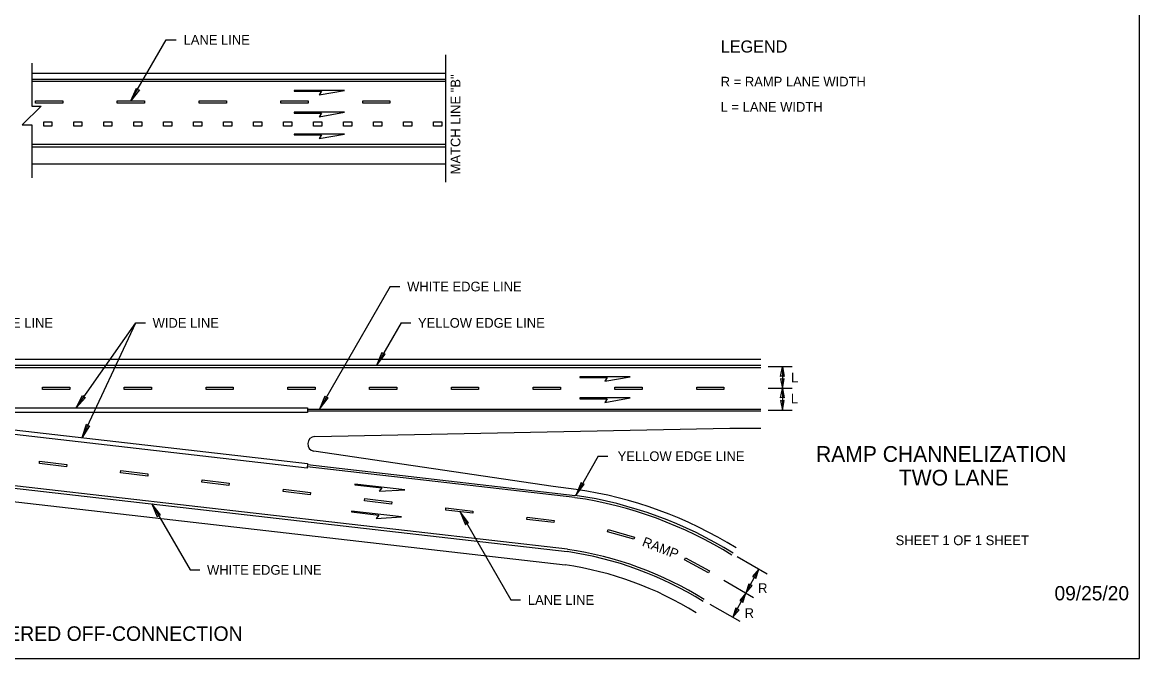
# Model space of a CAD drawing. Extents: x 99862 to 103151, y 100339 to 102415.
# Drawn here: x 101307 to 103151, y 100339 to 101389 of the extents above; entities that cross this region are included whole.
import ezdxf

# ---------------------------------------------------------------- set-up
doc = ezdxf.new("R2010")
doc.units = 0
for name, color, linetype in [('Level 1', 7, 'Continuous'), ('Level 15', 7, 'Continuous'), ('Level 2', 7, 'Continuous'), ('Level 20', 7, 'Continuous'), ('Level 3', 7, 'Continuous'), ('Level 4', 7, 'Continuous'), ('Level 5', 7, 'Continuous'), ('Level 6', 7, 'Continuous'), ('Level 62', 7, 'Continuous')]:
    doc.layers.add(name, color=color, linetype=linetype)

msp = doc.modelspace()

# ---------------------------------------------------------------- linework, layer by layer
at = {"layer": 'Level 1'}
msp.add_lwpolyline([(99862, 100338.8), (103151, 100338.8), (103151, 102414.8), (99862, 102414.8)], close=True, dxfattribs=at)
at = {"layer": 'Level 15'}
for p, q in [((101486, 101259.3), (101544.3, 101360.3)), ((101544.3, 101360.3), (101560.9, 101360.3)), ((101913.9, 100953), (101797.2, 100750.8)), ((101913.9, 100953), (101929.9, 100953)), ((101395.6, 100752.7), (101493.8, 100893)), ((101405.5, 100703.6), (101493.8, 100893)), ((101493.8, 100893), (101509.8, 100893)), ((101931.8, 100893), (101891.3, 100822.8)), ((101931.8, 100893), (101947.8, 100893)), ((102537.9, 100821), (102577.4, 100821)), ((102561.4, 100820.4), (102561.4, 100784.9)), ((102537.9, 100785), (102577.4, 100785)), ((102561.4, 100784.9), (102561.4, 100749)), ((102537.9, 100749), (102577.4, 100749)), ((102257.4, 100672.9), (102220.1, 100608.2)), ((102257.4, 100672.9), (102273.4, 100672.9)), ((101520.7, 100594.2), (101583.6, 100485.3)), ((102029.2, 100581.1), (102113.2, 100435.6)), ((102486.9, 100507.2), (102536.3, 100478.7)), ((101583.6, 100485.3), (101599.6, 100485.3)), ((102501, 100446.9), (102522.4, 100486.7)), ((102464.4, 100468.1), (102513.7, 100439.6)), ((102479.5, 100407.1), (102501, 100446.9)), ((102113.2, 100435.6), (102129.2, 100435.6)), ((102441.8, 100428.9), (102491.1, 100400.4))]:
    msp.add_line(p, q, dxfattribs=at)
for points in [[(101322.2, 101321.9), (101322.2, 101250.7), (101337.7, 101250.7), (101306.7, 101219.7), (101322.2, 101219.7), (101322.2, 101132.6)], [(101337.7, 101250.7), (101306.7, 101219.7)]]:
    msp.add_lwpolyline(points, dxfattribs=at)
for points in [[(101486, 101259.3), (101494.9, 101280.6), (101496.9, 101278.2), (101500.1, 101277.6)], [(101891.3, 100822.8), (101905.4, 100841.2), (101902.3, 100841.8), (101900.2, 100844.2)], [(102561.4, 100820.4), (102564.5, 100804.6), (102561.4, 100805.4), (102558.3, 100804.6)], [(102561.4, 100784.9), (102564.5, 100800.8), (102561.4, 100800), (102558.3, 100800.8)], [(101395.6, 100752.7), (101406.2, 100773.1), (101408.1, 100770.5), (101411.1, 100769.7)], [(101797.2, 100750.8), (101811.3, 100769.2), (101808.1, 100769.8), (101806.1, 100772.2)], [(102561.4, 100784.9), (102564.5, 100769.1), (102561.4, 100769.9), (102558.3, 100769.1)], [(102561.4, 100749), (102564.5, 100764.8), (102561.4, 100764), (102558.3, 100764.8)], [(101405.5, 100703.6), (101412.4, 100725.6), (101414.7, 100723.4), (101417.8, 100723.1)], [(102220.1, 100608.2), (102234.1, 100626.6), (102231, 100627.2), (102228.9, 100629.6)], [(101520.7, 100594.2), (101529.5, 100572.9), (101531.6, 100575.3), (101534.7, 100575.9)], [(102029.2, 100581.1), (102038, 100559.8), (102040.1, 100562.2), (102043.2, 100562.8)], [(102522.4, 100486.7), (102512.2, 100474.3), (102515.3, 100473.4), (102517.7, 100471.3)], [(102501, 100446.9), (102511.2, 100459.4), (102508.1, 100460.2), (102505.8, 100462.3)], [(102501, 100446.9), (102490.8, 100434.5), (102493.8, 100433.6), (102496.2, 100431.5)], [(102479.5, 100407.1), (102489.8, 100419.6), (102486.7, 100420.4), (102484.3, 100422.5)]]:
    msp.add_lwpolyline(points, close=True, dxfattribs=at)
at = {"layer": 'Level 2'}
for p, q in [((101322.3, 101305.4), (102005, 101305.4)), ((101322.2, 101155.4), (102005, 101155.4)), ((100315.1, 100833), (102525.9, 100833))]:
    msp.add_line(p, q, dxfattribs=at)
for points in [[(101789.5, 100705.3), (102474.7, 100719), (102525.9, 100719)], [(102220.8, 100618.2), (102182.7, 100622.7), (101787.9, 100681.4)], [(100315.1, 100673.7), (100633.4, 100673.7), (102202.6, 100493.5)]]:
    msp.add_lwpolyline(points, dxfattribs=at)
for centre, radius, start, end in [((101789.7, 100693.3), 12, 91.1458, 261.5415), ((102121.1, 99936), 689.4, 58.1228, 81.6857), ((102122.4, 99938.8), 560.5, 58.0828, 81.7749)]:
    msp.add_arc(centre, radius, start, end, dxfattribs=at)
at = {"layer": 'Level 3'}
for p, q in [((101322.3, 101295.3), (102005.8, 101295.3)), ((102005.8, 101291.5), (101322.3, 101291.5)), ((102005.8, 101187.3), (101322.2, 101187.3)), ((101322.2, 101183.5), (102005.8, 101183.5)), ((102525.9, 100822.8), (100315.1, 100822.8)), ((100315.1, 100819.1), (102525.9, 100819.1)), ((101777.7, 100750.8), (102525.9, 100750.8)), ((102525.9, 100747.1), (101777.7, 100747.1)), ((102218.8, 100604.6), (101777.1, 100655.3)), ((101777.6, 100659), (102219.3, 100608.3))]:
    msp.add_line(p, q, dxfattribs=at)
msp.add_lwpolyline([(101043.2, 100745.2), (101777.7, 100660.9), (101776.9, 100653.4), (100977.5, 100745.2), (100977.5, 100752.7), (101777.7, 100752.7), (101777.7, 100745.2)], close=True, dxfattribs=at)
for points in [[(102206.4, 100519.3), (100582.6, 100705.6), (100315.1, 100705.6)], [(100315.1, 100701.8), (100582.3, 100701.8), (102205.8, 100515.6)]]:
    msp.add_lwpolyline(points, dxfattribs=at)
for radius, start, end in [(675.6, 58.1147, 81.6808), (679.4, 58.1228, 81.6857), (585.7, 58.1147, 81.6808), (589.4, 58.1147, 81.6808)]:
    msp.add_arc((102121.1, 99936), radius, start, end, dxfattribs=at)
at = {"layer": 'Level 4'}
for points in [[(101328.5, 101259.3), (101373.5, 101259.3), (101373.5, 101255.5), (101328.5, 101255.5)], [(101463.5, 101259.3), (101508.5, 101259.3), (101508.5, 101255.5), (101463.5, 101255.5)], [(101598.5, 101259.3), (101643.5, 101259.3), (101643.5, 101255.5), (101598.5, 101255.5)], [(101733.5, 101259.3), (101778.5, 101259.3), (101778.5, 101255.5), (101733.5, 101255.5)], [(101868.5, 101259.3), (101913.5, 101259.3), (101913.5, 101255.5), (101868.5, 101255.5)], [(101342, 101225.1), (101355.5, 101225.1), (101355.5, 101217.6), (101342, 101217.6)], [(101391.5, 101225.1), (101405, 101225.1), (101405, 101217.6), (101391.5, 101217.6)], [(101441, 101225.1), (101454.5, 101225.1), (101454.5, 101217.6), (101441, 101217.6)], [(101490.5, 101225.1), (101504, 101225.1), (101504, 101217.6), (101490.5, 101217.6)], [(101540, 101225.1), (101553.5, 101225.1), (101553.5, 101217.6), (101540, 101217.6)], [(101589.5, 101225.1), (101603, 101225.1), (101603, 101217.6), (101589.5, 101217.6)], [(101639, 101225.1), (101652.5, 101225.1), (101652.5, 101217.6), (101639, 101217.6)], [(101688.5, 101225.1), (101702, 101225.1), (101702, 101217.6), (101688.5, 101217.6)], [(101738, 101225.1), (101751.5, 101225.1), (101751.5, 101217.6), (101738, 101217.6)], [(101787.5, 101225.1), (101801, 101225.1), (101801, 101217.6), (101787.5, 101217.6)], [(101837, 101225.1), (101850.5, 101225.1), (101850.5, 101217.6), (101837, 101217.6)], [(101886.5, 101225.1), (101900, 101225.1), (101900, 101217.6), (101886.5, 101217.6)], [(101936, 101225.1), (101949.5, 101225.1), (101949.5, 101217.6), (101936, 101217.6)], [(101985.5, 101225.1), (101999, 101225.1), (101999, 101217.6), (101985.5, 101217.6)], [(101339.9, 100786.8), (101384.9, 100786.8), (101384.9, 100783.1), (101339.9, 100783.1)], [(101474.9, 100786.8), (101519.9, 100786.8), (101519.9, 100783.1), (101474.9, 100783.1)], [(101609.9, 100786.8), (101654.9, 100786.8), (101654.9, 100783.1), (101609.9, 100783.1)], [(101744.9, 100786.8), (101789.9, 100786.8), (101789.9, 100783.1), (101744.9, 100783.1)], [(101879.9, 100786.8), (101924.9, 100786.8), (101924.9, 100783.1), (101879.9, 100783.1)], [(102014.9, 100786.8), (102059.9, 100786.8), (102059.9, 100783.1), (102014.9, 100783.1)], [(102149.9, 100786.8), (102194.9, 100786.8), (102194.9, 100783.1), (102149.9, 100783.1)], [(102284.9, 100786.8), (102329.9, 100786.8), (102329.9, 100783.1), (102284.9, 100783.1)], [(102419.9, 100786.8), (102464.9, 100786.8), (102464.9, 100783.1), (102419.9, 100783.1)], [(101335.3, 100664.5), (101380, 100659.4), (101379.6, 100655.6), (101334.9, 100660.8)], [(101469.4, 100649.1), (101514.1, 100644), (101513.7, 100640.2), (101469, 100645.4)], [(101603.5, 100633.7), (101648.2, 100628.6), (101647.8, 100624.8), (101603.1, 100630)], [(101737.7, 100618.3), (101782.4, 100613.2), (101781.9, 100609.4), (101737.2, 100614.6)], [(101871.8, 100602.9), (101916.5, 100597.8), (101916.1, 100594), (101871.3, 100599.2)], [(102005.9, 100587.5), (102050.6, 100582.4), (102050.2, 100578.7), (102005.5, 100583.8)], [(102140, 100572.1), (102184.7, 100567), (102184.3, 100563.3), (102139.6, 100568.4)], [(102273.9, 100551.8), (102317.2, 100539.5), (102316.1, 100535.9), (102272.8, 100548.2)], [(102401.4, 100505.2), (102441, 100483.9), (102439.2, 100480.5), (102399.6, 100501.9)]]:
    msp.add_lwpolyline(points, close=True, dxfattribs=at)
at = {"layer": 'Level 5'}
for points in [[(101755.3, 101275.4), (101800.4, 101275.4), (101796.8, 101269.2), (101838.4, 101276.6), (101755.3, 101276.6)], [(101755.3, 101239.4), (101800.4, 101239.4), (101796.8, 101233.2), (101838.4, 101240.6), (101755.3, 101240.6)], [(101755.3, 101203.4), (101800.4, 101203.4), (101796.8, 101197.2), (101838.4, 101204.6), (101755.3, 101204.6)], [(102226.8, 100803), (102271.9, 100803), (102268.3, 100796.8), (102309.8, 100804.1), (102226.8, 100804.1)], [(102226.7, 100767.9), (102271.8, 100767.9), (102268.2, 100761.7), (102309.8, 100769.1), (102226.7, 100769.1)], [(101855.3, 100625.9), (101900, 100620.7), (101895.8, 100615), (101937.9, 100617.6), (101855.4, 100627)], [(101850.1, 100580.9), (101894.9, 100575.8), (101890.7, 100570), (101932.7, 100572.6), (101850.2, 100582.1)]]:
    msp.add_lwpolyline(points, close=True, dxfattribs=at)
at = {"layer": 'Level 6'}
msp.add_line((102005.8, 101125.4), (102005.8, 101335.4), dxfattribs=at)

# ---------------------------------------------------------------- texts
at = {"layer": 'Level 15'}
msp.add_text('09/25/20', height=23.62, dxfattribs=at).set_placement((103010.5, 100435))
at = {"layer": 'Level 20'}
for s, height, p in [('LANE LINE', 16, (101572.9, 101352.3)), ('LEGEND', 20, (102459.5, 101339.2)), ('R = RAMP LANE WIDTH', 16, (102459.5, 101283.2)), ('L = LANE WIDTH', 16, (102459.5, 101241.5)), ('WHITE EDGE LINE', 16, (101941.9, 100945)), ('LANE LANE LINE', 16, (101186.2, 100885)), ('WIDE LINE', 16, (101521.8, 100885)), ('YELLOW EDGE LINE', 16, (101959.8, 100885)), ('L', 16, (102575.6, 100794.8)), ('L', 16, (102575.2, 100760.2)), ('YELLOW EDGE LINE', 16, (102289.4, 100664.9)), ('WHITE EDGE LINE', 16, (101611.6, 100477.3)), ('R', 16, (102521.2, 100447.1)), ('LANE LINE', 16, (102141.2, 100427.6)), ('R', 16, (102498.9, 100406)), ('TWO-LANE TAPERED OFF-CONNECTION', 24, (101041, 100368.1))]:
    msp.add_text(s, height=height, dxfattribs=at).set_placement(p)
for s, rotation, p in [('MATCH LINE "B"', 90, (102029.8, 101138.1)), ('RAMP', 338.7717, (102328.5, 100525.4))]:
    msp.add_text(s, height=16, rotation=rotation, dxfattribs=at).set_placement(p)
at = {"layer": 'Level 62'}
for s, height, p in [('RAMP CHANNELIZATION', 26, (102616.8, 100663.6)), ('TWO LANE', 26, (102753.6, 100624.6)), ('SHEET 1 OF 1 SHEET', 16, (102748.2, 100526.1))]:
    msp.add_text(s, height=height, dxfattribs=at).set_placement(p)

doc.saveas('drawing.dxf')
